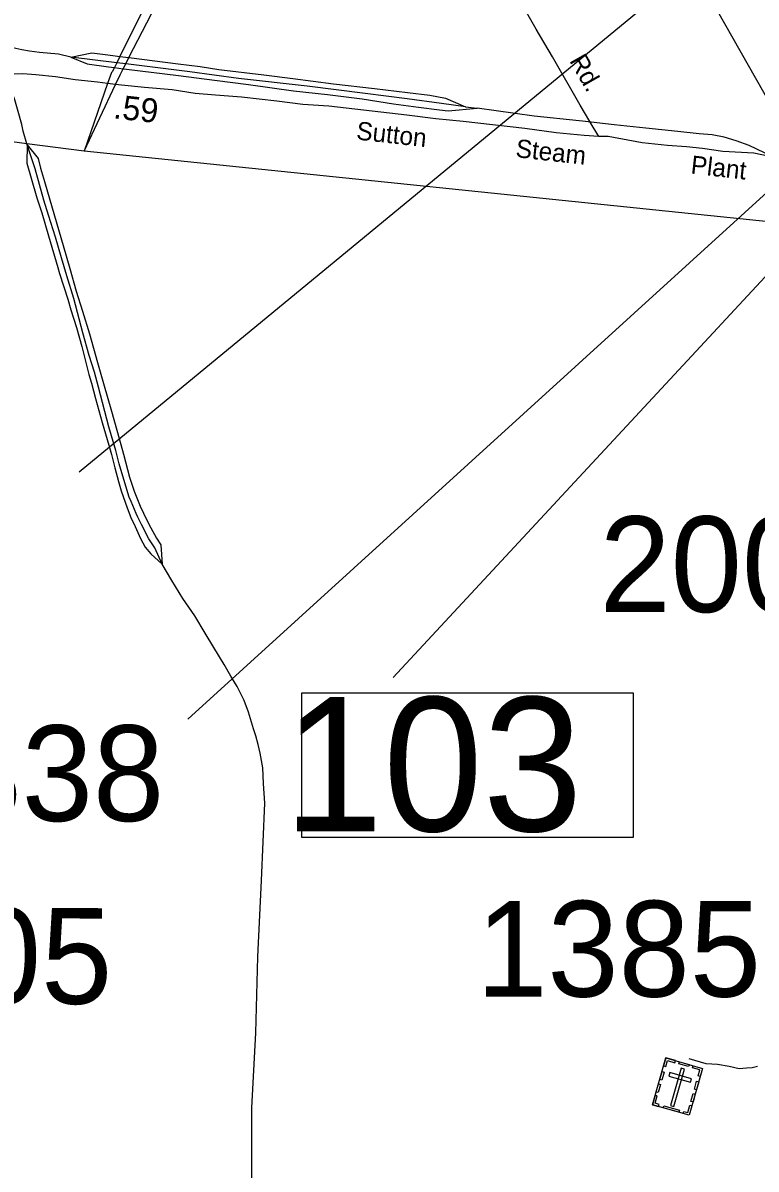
# Model space of a CAD drawing. Extents: x 2290055 to 2389491, y 66597 to 237875.
# Drawn here: x 2307682 to 2311511, y 190299 to 196284 of the extents above; entities that cross this region are included whole.
import ezdxf

# ---------------------------------------------------------------- set-up
doc = ezdxf.new("R2010")
doc.units = 0
for name, color, linetype in [('Exist Cultural Cemetery CELL', 7, 'Continuous'), ('Exist Railroad Mainline', 7, 'Continuous'), ('Exist Railroad Siding', 7, 'Continuous'), ('Exist Road Non-System Type 51 Label', 7, 'Continuous'), ('Exist Road Primary Interstate Structure Standard Bridge Number Label', 7, 'Continuous'), ('Exist Road Secondary Mileage Hundredths English Label', 7, 'Continuous'), ('Exist Road Secondary Type 51 Attributed', 7, 'Continuous'), ('Exist Road Secondary Type 51 Label', 7, 'Continuous'), ('Exist Road Secondary Type 51 Number Label', 7, 'Continuous'), ('Exist Utilities Electrical Transmission Line', 7, 'Continuous')]:
    doc.layers.add(name, color=color, linetype=linetype)

msp = doc.modelspace()

# ---------------------------------------------------------------- linework, layer by layer
at = {"layer": 'Exist Cultural Cemetery CELL'}
for points in [[(2311040.5, 190879.8), (2311231.9, 190825.1), (2311161.9, 190580.3), (2310970.5, 190635)], [(2311028.5, 190838.2), (2311039.5, 190835.1), (2311048.3, 190866), (2311087.3, 190854.9), (2311090.4, 190865.6), (2311040.5, 190879.8)], [(2311111.7, 190859.5), (2311161.5, 190845.2), (2311158.4, 190834.3), (2311108.5, 190848.5)], [(2311008.2, 190766.9), (2311020.1, 190808.5), (2311031, 190805.4), (2311019.1, 190763.8)], [(2311061, 190803.2), (2311055.9, 190785.2), (2311169.1, 190752.9), (2311174.2, 190770.8)], [(2311137.2, 190821.7), (2311119.3, 190826.8), (2311063.5, 190631.9), (2311081.5, 190626.7)], [(2311220, 190783.4), (2311209.1, 190786.5), (2311218, 190817.5), (2311179, 190828.6), (2311182, 190839.3), (2311231.9, 190825.1)], [(2310989.7, 190702.3), (2311001.6, 190743.9), (2311012.5, 190740.8), (2311000.6, 190699.1)], [(2311189, 190716.3), (2311200.9, 190757.9), (2311211.8, 190754.8), (2311199.9, 190713.2)], [(2311002.3, 190626), (2311005.5, 190637), (2310984.3, 190643.1), (2310995.4, 190681.9), (2310984.7, 190685), (2310970.4, 190635.1)], [(2311170.8, 190652.9), (2311182.7, 190694.6), (2311193.7, 190691.4), (2311181.8, 190649.8)], [(2311028.9, 190630.3), (2311110.5, 190606.9), (2311107.3, 190596), (2311025.7, 190619.3)], [(2311130, 190589.4), (2311133.2, 190600.5), (2311154.4, 190594.4), (2311165.5, 190633.3), (2311176.2, 190630.2), (2311161.9, 190580.3)]]:
    msp.add_lwpolyline(points, close=True, dxfattribs=at)
at = {"layer": 'Exist Railroad Mainline'}
for points in [[(2311748.8, 195574.5), (2310677.6, 197461), (2310543.5, 197697.2), (2309738.8, 199121.3), (2309709.2, 199173.6), (2309672.1, 199239.2), (2309406.8, 199708.8)], [(2307932.8, 196105.2), (2307868.5, 196120.3), (2307768.5, 196129.1), (2307716.4, 196136.5), (2307676.3, 196143.9), (2307630.1, 196153.3), (2307596, 196166.9), (2307541.7, 196188.2), (2307485.4, 196221.3), (2307407, 196256.4)], [(2309993.7, 195846), (2309867.5, 195864.2), (2309689.1, 195888), (2309468.9, 195915.3), (2309166.5, 195953.3), (2308807.9, 195994.5), (2308553.6, 196029.2), (2308218.9, 196070.2), (2308172.3, 196075.9), (2307932.8, 196105.2)], [(2307704.6, 195647.4), (2307702.8, 195653.6), (2307683.8, 195718.6), (2307676.4, 195754.4), (2307657.7, 195821.6), (2307639.2, 195882.9), (2307591.1, 196015.1)], [(2310604.8, 195770.8), (2310587.2, 195772.7), (2310352.2, 195796.6), (2310053.8, 195838.8)], [(2311589, 195587.9), (2311555, 195605.1), (2311475.9, 195643.3), (2311407.5, 195668), (2311345.3, 195687.6), (2311281.1, 195700.6), (2311213.1, 195705.7), (2311103.1, 195716.4), (2310934.9, 195734.1), (2310770.7, 195752), (2310604.8, 195770.8)], [(2308409.7, 193458.7), (2308370.3, 193543.2), (2308340.4, 193590), (2308301.5, 193664.5), (2308281.9, 193703.7), (2308273.1, 193723.4), (2308246.7, 193784.4), (2308237.7, 193808), (2308224.2, 193847.5), (2308184.8, 193982), (2308168.1, 194051.3), (2308131.1, 194175.9), (2308076.9, 194381.8), (2308055.8, 194461), (2308028.3, 194547.9), (2307995.6, 194666.7), (2307948.5, 194844.9), (2307911.8, 194963.5), (2307884, 195058.4), (2307851.8, 195165.1), (2307815.2, 195279.7), (2307792.1, 195358.8), (2307745.6, 195523), (2307704.6, 195647.4)], [(2308876.9, 190207.3), (2308877.6, 190619.2), (2308898.5, 191011.6), (2308909.4, 191407.7), (2308928.2, 191806), (2308945, 192210.2), (2308939.3, 192313.4), (2308934.7, 192394), (2308921, 192470.7), (2308911.2, 192516.3), (2308898.4, 192561.6), (2308886, 192597.6), (2308860.9, 192685.2), (2308838.1, 192745.5), (2308801.1, 192820.1), (2308768.4, 192874), (2308733.6, 192933.4), (2308678.4, 193022.9), (2308633.6, 193098.3), (2308580.5, 193187.4), (2308517.2, 193278.7), (2308460.1, 193371.9), (2308409.7, 193458.7)]]:
    msp.add_lwpolyline(points, dxfattribs=at)
at = {"layer": 'Exist Railroad Siding'}
msp.add_line((2309993.7, 195846), (2310053.8, 195838.8), dxfattribs=at)
for points in [[(2307932.8, 196105.2), (2308042.5, 196128.6), (2308112.5, 196119.6), (2308152.5, 196114.1), (2308188.9, 196109.5), (2308236, 196103.4), (2308493.2, 196070.4), (2308607.2, 196055.9), (2308705.4, 196041.2), (2308939.6, 196012.3), (2309091.8, 195994.3), (2309304.2, 195967), (2309518.5, 195941.8), (2309690.8, 195920.1), (2309806.9, 195907.7), (2309889.1, 195890.7), (2309993.7, 195846)], [(2307932.8, 196105.2), (2308017.2, 196070.4), (2308129.4, 196055.8), (2308160.2, 196051.6), (2308206.1, 196045.3), (2308223.5, 196042.9), (2308493.9, 196010.4), (2308682, 195984.9), (2308860.4, 195963.4), (2309094.8, 195930.2), (2309273, 195910.7), (2309453.2, 195887), (2309617.5, 195861.1), (2309747.6, 195844.7), (2309857.8, 195830.3), (2309903.9, 195824.9), (2310053.8, 195838.8)], [(2307704.6, 195647.4), (2307702.4, 195551.3), (2307725.5, 195474.2), (2307755.6, 195371.4), (2307780.7, 195292.4), (2307815.5, 195171.7), (2307864, 195007.6), (2307873.3, 194975.9), (2307916.6, 194841.6), (2307932.8, 194786.2), (2307962.5, 194693.4), (2307990.5, 194594.5), (2308026.3, 194447.8), (2308040.1, 194402.4), (2308061.3, 194323.2), (2308096.2, 194198.5), (2308130.9, 194079.9), (2308144.9, 194030.4), (2308161.6, 193961.1), (2308180.5, 193889.8), (2308194.4, 193840.3), (2308226, 193751.5), (2308245.9, 193702.3), (2308267.8, 193655.2), (2308296.3, 193592.3), (2308320.1, 193547.2), (2308349.5, 193512.4), (2308409.7, 193458.7)], [(2307704.6, 195647.4), (2307761.5, 195575.7), (2307773.4, 195526.1), (2307794.2, 195456.9), (2307859, 195235.4), (2307891.5, 195122.7), (2307926.3, 195002), (2307961, 194883.4), (2307993.2, 194778.6), (2308029.9, 194660), (2308071.8, 194511.7), (2308106.7, 194389), (2308141.5, 194268.3), (2308176.3, 194145.7), (2308206.8, 194032.9), (2308239.6, 193912.1), (2308262.5, 193839), (2308293.7, 193760.2), (2308328.6, 193687.6), (2308350.1, 193648.4), (2308380.3, 193593.6), (2308401.7, 193558.4), (2308409.7, 193458.7)]]:
    msp.add_lwpolyline(points, dxfattribs=at)
at = {"layer": 'Exist Road Primary Interstate Structure Standard Bridge Number Label'}
msp.add_lwpolyline([(2312310.1, 198469.7), (2313026.1, 196540.1), (2309615.3, 192866.9)], dxfattribs=at)
msp.add_lwpolyline([(2310870.6, 192783.8), (2309137.7, 192783.8), (2309137.7, 192032.5), (2310870.6, 192032.5)], close=True, dxfattribs=at)
at = {"layer": 'Exist Road Secondary Type 51 Attributed'}
for points in [[(2310642.5, 195769.7), (2310592, 195854.1), (2310447.9, 196107.3), (2310363.4, 196251.9), (2310277.9, 196401.1), (2310199.9, 196536.7), (2310090.5, 196733.4), (2309958.5, 196962.4), (2309869, 197127.1)], [(2310690, 195691.1), (2310613.8, 195696.8), (2310467.2, 195711), (2310304.3, 195732.5), (2309980.7, 195769.7), (2309838.1, 195784.1), (2309687.3, 195802.1), (2309279.2, 195849.9), (2309144.8, 195858.6), (2309008.1, 195875.2), (2308823.2, 195895.9), (2308688.7, 195906.5), (2308582.3, 195916.3), (2308461.5, 195935.5), (2308317, 195947.8), (2308196.5, 195959), (2308165.8, 195962.7), (2308124.2, 195967.8), (2308071.8, 195974.1), (2307955.2, 195987.5), (2307852.6, 196003.4), (2307750.1, 196013.4), (2307681.9, 196018.7), (2307591.1, 196015.1)], [(2310690, 195691.1), (2310645.2, 195766.2)], [(2311589, 195587.9), (2311574.5, 195588.8), (2311499.9, 195603.9), (2311337.4, 195613.4), (2311230.8, 195629.2), (2311148.4, 195638), (2311048.1, 195644), (2310915.5, 195658.7), (2310739.4, 195691.1), (2310690, 195691.1)], [(2311518.9, 190835.2), (2311490.3, 190828), (2311461.2, 190826.9), (2311423.3, 190823.4), (2311370.8, 190835.3), (2311310.4, 190844.9), (2311250.3, 190848.5), (2311161.2, 190875)]]:
    msp.add_lwpolyline(points, dxfattribs=at)
at = {"layer": 'Exist Road Secondary Type 51 Number Label'}
msp.add_line((2311823.6, 197108.6), (2307975.4, 193938.2), dxfattribs=at)
msp.add_lwpolyline([(2312304.6, 197327.2), (2312916.8, 196627.6), (2308543.9, 192648.2)], dxfattribs=at)
at = {"layer": 'Exist Utilities Electrical Transmission Line'}
for p, q in [((2309225.2, 198198.1), (2308188.9, 196109.5)), ((2308172.3, 196075.9), (2308160.2, 196051.6)), ((2308188.9, 196109.5), (2308172.3, 196075.9)), ((2308206.1, 196045.3), (2308218.9, 196070.2)), ((2308218.9, 196070.2), (2308236, 196103.4)), ((2308124.2, 195967.8), (2308001.8, 195614.8)), ((2308001.8, 195614.8), (2308165.8, 195962.7)), ((2307702.8, 195653.6), (2307117.1, 195729.7)), ((2308001.8, 195614.8), (2307702.8, 195653.6)), ((2311956.6, 195206.4), (2308001.8, 195614.8))]:
    msp.add_line(p, q, dxfattribs=at)
for points in [[(2308236, 196103.4), (2308400.3, 196423.1), (2309255.6, 198147.3)], [(2308160.2, 196051.6), (2308148.5, 196028), (2308144.4, 196026), (2308124.2, 195967.8)], [(2308165.8, 195962.7), (2308189.7, 196013.4), (2308206.1, 196045.3)]]:
    msp.add_lwpolyline(points, dxfattribs=at)

# ---------------------------------------------------------------- texts
at = {"layer": 'Exist Road Non-System Type 51 Label'}
msp.add_text('Rd.', height=95, rotation=299.59563, dxfattribs=at).set_placement((2310533.8, 196087.2))
at = {"layer": 'Exist Road Primary Interstate Structure Standard Bridge Number Label'}
msp.add_text('103', height=700, dxfattribs=at).set_placement((2309042.9, 192063.6))
at = {"layer": 'Exist Road Secondary Mileage Hundredths English Label'}
for s, height, rotation, p in [('.59', 125, 353.6789, (2308151, 195786.6)), ('.05', 500, 359.79739, (2307218.7, 191164.8))]:
    msp.add_text(s, height=height, rotation=rotation, dxfattribs=at).set_placement(p)
at = {"layer": 'Exist Road Secondary Type 51 Label'}
for s, rotation, p in [('Sutton', 353.6789, (2309420.2, 195675.9)), ('Steam', 353.6789, (2310252.5, 195583.7)), ('Plant', 353.67277, (2311167.1, 195498))]:
    msp.add_text(s, height=95, rotation=rotation, dxfattribs=at).set_placement(p)
at = {"layer": 'Exist Road Secondary Type 51 Number Label'}
for s, p in [('2000', (2310693.6, 193207.8)), ('2838', (2306932.4, 192116.7)), ('1385', (2310049.6, 191199.8))]:
    msp.add_text(s, height=500, dxfattribs=at).set_placement(p)

doc.saveas('drawing.dxf')
